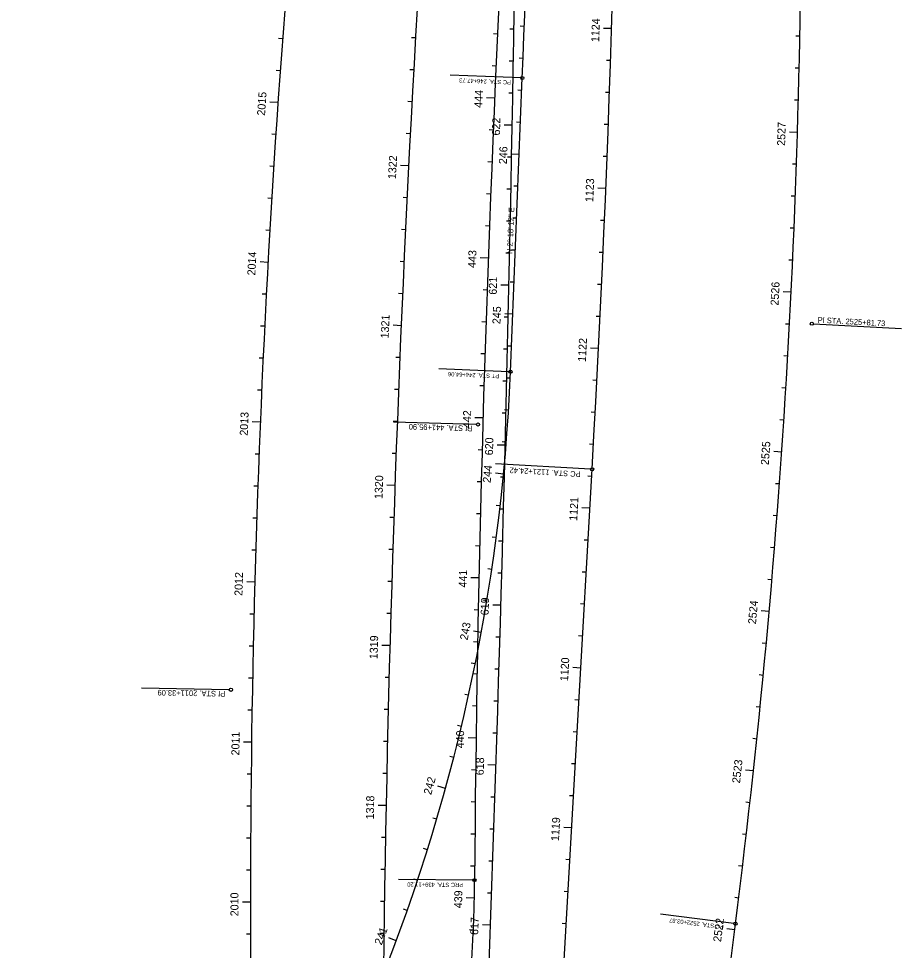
# Model space of a CAD drawing. Extents: x 919452 to 931278, y 583254 to 665650.
# Drawn here: x 928794 to 929346, y 637530 to 638112 of the extents above; entities that cross this region are included whole.
import ezdxf

# ---------------------------------------------------------------- set-up
doc = ezdxf.new("R2010")
doc.units = 0
for name, color, linetype in [('CLConst_dp', 7, 'Continuous'), ('CurveDataLabel_dp', 7, 'Continuous'), ('StationTicL_dp', 7, 'Continuous'), ('StationTicS_dp', 7, 'Continuous'), ('TextBLStation', 7, 'Continuous'), ('TextLabel', 7, 'Continuous')]:
    doc.layers.add(name, color=color, linetype=linetype)

msp = doc.modelspace()

# ---------------------------------------------------------------- linework, layer by layer
at = {"layer": 'CLConst_dp'}
for p, q in [((929101.42, 637891.3), (929108.8, 638074.83)), ((929063.91, 636273.75), (929152.38, 637830.35)), ((929141.47, 636757.31), (929241.91, 637546.46))]:
    msp.add_line(p, q, dxfattribs=at)
for centre, radius, start, end in [((918208.05, 638452.43), 10962, 356.746791, 3.806041), ((914272.82, 638671.54), 14847.97, 357.696753, 0.946314), ((900459.43, 638571.38), 28647.89, 355.955427, 0.622371), ((942221.08, 637355.55), 13200, 175.794488, 180.562502), ((924158.91, 638193.39), 5124, 352.74679, 1.18191), ((942581.4, 637470.03), 13502.86, 177.14455, 179.560307), ((936146.52, 637562.53), 7207.49, 175.47906, 182.456288), ((927949.43, 637937.64), 1152.92, 317.11857, 357.69675), ((928044.2, 637581.6), 1034.77, 344.85215, 359.56031)]:
    msp.add_arc(centre, radius, start, end, dxfattribs=at)
at = {"layer": 'CurveDataLabel_dp'}
for p, q in [((929107.8, 638074.87), (929063.82, 638076.64)), ((929290.62, 637921.24), (929345.52, 637918.33)), ((929100.42, 637891.34), (929056.57, 637893.11)), ((929080.12, 637858.38), (929028.39, 637859.87)), ((929151.39, 637830.41), (929091.99, 637833.78)), ((928925.82, 637692.64), (928870.93, 637693.63)), ((929077.93, 637573.66), (929031.41, 637574.02)), ((929240.92, 637546.59), (929195.04, 637552.42))]:
    msp.add_line(p, q, dxfattribs=at)
for centre in [(929108.8, 638074.83), (929289.62, 637921.3), (929101.42, 637891.3), (929081.12, 637858.35), (929152.38, 637830.35), (928926.82, 637692.63), (929078.93, 637573.66), (929241.91, 637546.46)]:
    msp.add_circle(centre, 1, dxfattribs=at)
at = {"layer": 'StationTicL_dp'}
for p, q in [((929164.56, 638105.66), (929159.57, 638105.81)), ((928956.18, 638059.45), (928951.19, 638059.79)), ((929091.53, 638062.27), (929086.53, 638062.49)), ((929102.49, 638045.33), (929097.49, 638045.42)), ((929280.64, 638040.88), (929275.65, 638041.03)), ((929106.88, 638027.13), (929101.88, 638027.33)), ((929037.81, 638019.97), (929032.82, 638020.23)), ((929160.94, 638005.72), (929155.95, 638005.92)), ((928949.97, 637959.64), (928944.98, 637959.92)), ((929087.51, 637962.35), (929082.52, 637962.53)), ((929100.47, 637945.35), (929095.48, 637945.46)), ((929276.69, 637940.96), (929271.7, 637941.21)), ((929102.86, 637927.21), (929097.87, 637927.41)), ((929033.15, 637920.08), (929028.16, 637920.3)), ((929156.41, 637905.82), (929151.42, 637906.07)), ((929084.24, 637862.41), (929079.24, 637862.55)), ((928945.16, 637859.76), (928940.16, 637859.96)), ((929098.12, 637845.37), (929093.12, 637845.5)), ((929270.79, 637841.14), (929265.8, 637841.48)), ((929097.07, 637827.4), (929092.09, 637827.87)), ((929029.26, 637820.16), (929024.26, 637820.34)), ((929151, 637805.97), (929146.01, 637806.25)), ((929081.7, 637762.44), (929076.7, 637762.55)), ((928941.73, 637759.82), (928936.73, 637759.96)), ((929095.41, 637745.41), (929090.41, 637745.55)), ((929262.94, 637741.45), (929257.96, 637741.89)), ((929083.2, 637728.39), (929078.29, 637729.3)), ((929026.11, 637720.21), (929021.12, 637720.35)), ((929145.32, 637706.13), (929140.33, 637706.42)), ((928939.68, 637659.84), (928934.68, 637659.91)), ((929079.91, 637662.45), (929074.91, 637662.53)), ((929092.35, 637645.46), (929087.35, 637645.62)), ((929253.15, 637641.93), (929248.18, 637642.47)), ((929060.81, 637630.96), (929055.99, 637632.29)), ((929023.73, 637620.24), (929018.73, 637620.34)), ((929139.65, 637606.29), (929134.66, 637606.58)), ((928939.03, 637559.84), (928934.03, 637559.84)), ((929078.79, 637562.46), (929073.79, 637562.55)), ((929088.94, 637545.52), (929083.95, 637545.69)), ((929241.42, 637542.62), (929236.46, 637543.25)), ((929030.07, 637535.84), (929025.38, 637537.58))]:
    msp.add_line(p, q, dxfattribs=at)
at = {"layer": 'StationTicS_dp'}
for p, q in [((929103.52, 638105.32), (929101.02, 638105.36)), ((929110.06, 638107.07), (929107.56, 638107.16)), ((928959.04, 638099.35), (928956.55, 638099.53)), ((929042.08, 638099.86), (929039.58, 638100)), ((929093.34, 638102.23), (929090.84, 638102.35)), ((929282.08, 638100.87), (929279.58, 638100.91)), ((929092.42, 638082.25), (929089.92, 638082.36)), ((929103.19, 638085.32), (929100.69, 638085.36)), ((929109.29, 638087.08), (929106.79, 638087.18)), ((929163.91, 638085.67), (929161.41, 638085.75)), ((928957.58, 638079.4), (928955.09, 638079.58)), ((929040.97, 638079.89), (929038.47, 638080.03)), ((929281.68, 638080.87), (929279.18, 638080.92)), ((929102.85, 638065.32), (929100.35, 638065.37)), ((929108.49, 638067.1), (929105.99, 638067.2)), ((929163.22, 638065.68), (929160.73, 638065.77)), ((929039.88, 638059.92), (929037.39, 638060.05)), ((929281.2, 638060.88), (929278.7, 638060.94)), ((929107.68, 638047.11), (929105.19, 638047.22)), ((929090.67, 638042.29), (929088.17, 638042.4)), ((929162.5, 638045.69), (929160, 638045.78)), ((928954.82, 638039.49), (928952.33, 638039.66)), ((929038.83, 638039.95), (929036.33, 638040.08)), ((929102.11, 638025.33), (929099.61, 638025.38)), ((929161.74, 638025.71), (929159.24, 638025.8)), ((928953.53, 638019.54), (928951.03, 638019.69)), ((929089.83, 638022.31), (929087.33, 638022.41)), ((929280.01, 638020.89), (929277.51, 638020.98)), ((929106.08, 638007.15), (929103.58, 638007.25)), ((929089.03, 638002.32), (929086.53, 638002.42)), ((929101.72, 638005.33), (929099.22, 638005.38)), ((929279.3, 638000.91), (929276.8, 638001)), ((928952.29, 637999.57), (928949.79, 637999.73)), ((929036.82, 638000), (929034.32, 638000.12)), ((929101.32, 637985.34), (929098.82, 637985.39)), ((929105.27, 637987.16), (929102.78, 637987.26)), ((929160.11, 637985.74), (929157.61, 637985.85)), ((928951.1, 637979.61), (928948.61, 637979.75)), ((929035.86, 637980.02), (929033.36, 637980.14)), ((929088.26, 637982.34), (929085.76, 637982.43)), ((929278.51, 637980.92), (929276.01, 637981.03)), ((929100.9, 637965.34), (929098.41, 637965.39)), ((929104.47, 637967.18), (929101.97, 637967.28)), ((929159.24, 637965.76), (929156.74, 637965.87)), ((929034.93, 637960.04), (929032.43, 637960.16)), ((929277.64, 637960.94), (929275.14, 637961.05)), ((929086.8, 637942.36), (929084.3, 637942.45)), ((929103.67, 637947.2), (929101.17, 637947.3)), ((929158.33, 637945.78), (929155.84, 637945.89)), ((928948.9, 637939.67), (928946.4, 637939.8)), ((929034.02, 637940.06), (929031.53, 637940.18)), ((929100.03, 637925.35), (929097.53, 637925.41)), ((929157.39, 637925.8), (929154.89, 637925.92)), ((928947.88, 637919.7), (928945.38, 637919.82)), ((929086.11, 637922.38), (929083.61, 637922.46)), ((929275.67, 637920.99), (929273.17, 637921.12)), ((929102.06, 637907.23), (929099.56, 637907.33)), ((929085.46, 637902.39), (929082.96, 637902.47)), ((929099.57, 637905.36), (929097.07, 637905.41)), ((928946.92, 637899.72), (928944.42, 637899.84)), ((929032.31, 637900.1), (929029.82, 637900.2)), ((929274.57, 637901.02), (929272.07, 637901.16)), ((929099.1, 637885.36), (929096.6, 637885.42)), ((929101.25, 637887.24), (929098.75, 637887.35)), ((929155.4, 637885.85), (929152.9, 637885.98)), ((928946.01, 637879.74), (928943.51, 637879.85)), ((929031.5, 637880.12), (929029.01, 637880.22)), ((929084.83, 637882.4), (929082.33, 637882.47)), ((929273.39, 637881.05), (929270.89, 637881.21)), ((929100.2, 637867.27), (929097.7, 637867.42)), ((929098.62, 637865.37), (929096.12, 637865.43)), ((929154.35, 637865.88), (929151.85, 637866.01)), ((929272.13, 637861.09), (929269.63, 637861.26)), ((929030.72, 637860.13), (929028.23, 637860.23)), ((929098.81, 637847.32), (929096.31, 637847.52)), ((929153.26, 637845.91), (929150.76, 637846.05)), ((928944.36, 637839.77), (928941.86, 637839.87)), ((929029.98, 637840.15), (929027.48, 637840.24)), ((929083.67, 637842.41), (929081.17, 637842.48)), ((929152.13, 637825.94), (929149.64, 637826.08)), ((928943.62, 637819.79), (928941.12, 637819.88)), ((929083.13, 637822.42), (929080.63, 637822.49)), ((929097.6, 637825.38), (929095.1, 637825.45)), ((929269.38, 637821.19), (929266.88, 637821.37)), ((929082.63, 637802.43), (929080.13, 637802.49)), ((929094.98, 637807.51), (929092.5, 637807.79)), ((929097.07, 637805.39), (929094.57, 637805.45)), ((928942.93, 637799.8), (928940.43, 637799.88)), ((929028.57, 637800.17), (929026.07, 637800.26)), ((929267.89, 637801.24), (929265.39, 637801.44)), ((929092.55, 637787.65), (929090.07, 637787.98)), ((929096.53, 637785.39), (929094.03, 637785.46)), ((929149.86, 637786), (929147.37, 637786.15)), ((928942.3, 637779.81), (928939.8, 637779.89)), ((929027.91, 637780.18), (929025.41, 637780.26)), ((929082.15, 637782.43), (929079.65, 637782.49)), ((929266.32, 637781.31), (929263.82, 637781.51)), ((929089.78, 637767.85), (929087.31, 637768.22)), ((929095.98, 637765.4), (929093.48, 637765.47)), ((929148.73, 637766.04), (929146.23, 637766.18)), ((929027.28, 637760.19), (929024.78, 637760.27)), ((929264.67, 637761.37), (929262.18, 637761.58)), ((929086.66, 637748.09), (929084.2, 637748.5)), ((929147.59, 637746.07), (929145.1, 637746.21)), ((928941.21, 637739.83), (928938.71, 637739.89)), ((929026.68, 637740.2), (929024.18, 637740.27)), ((929081.28, 637742.44), (929078.78, 637742.49)), ((929080.89, 637722.45), (929078.39, 637722.49)), ((929094.82, 637725.42), (929092.32, 637725.49)), ((929146.46, 637726.1), (929143.96, 637726.24)), ((929261.14, 637721.53), (929258.65, 637721.76)), ((928940.74, 637719.83), (928938.24, 637719.88)), ((929079.4, 637708.76), (929076.95, 637709.26)), ((929094.23, 637705.43), (929091.73, 637705.5)), ((928940.33, 637699.83), (928937.83, 637699.88)), ((929025.58, 637700.22), (929023.08, 637700.28)), ((929080.53, 637702.45), (929078.03, 637702.49)), ((929259.26, 637701.62), (929256.77, 637701.86)), ((929075.26, 637689.19), (929072.82, 637689.73)), ((929144.19, 637686.16), (929141.69, 637686.31)), ((929025.07, 637680.22), (929022.57, 637680.28)), ((929080.2, 637682.45), (929077.71, 637682.49)), ((929093.61, 637685.44), (929091.11, 637685.51)), ((929257.3, 637681.71), (929254.81, 637681.96)), ((928939.98, 637679.84), (928937.48, 637679.88)), ((929070.78, 637669.7), (929068.35, 637670.28)), ((929092.99, 637665.45), (929090.49, 637665.53)), ((929143.05, 637666.2), (929140.56, 637666.34)), ((929024.59, 637660.23), (929022.09, 637660.29)), ((929255.27, 637661.82), (929252.78, 637662.08)), ((929065.97, 637650.29), (929063.54, 637650.91)), ((929141.92, 637646.23), (929139.42, 637646.37)), ((928939.44, 637639.84), (928936.94, 637639.87)), ((929024.15, 637640.23), (929021.65, 637640.29)), ((929079.63, 637642.46), (929077.14, 637642.49)), ((929079.39, 637622.46), (929076.89, 637622.49)), ((929091.7, 637625.47), (929089.2, 637625.55)), ((929140.78, 637626.26), (929138.29, 637626.4)), ((929250.96, 637622.05), (929248.48, 637622.33)), ((928939.25, 637619.84), (928936.75, 637619.86)), ((929055.33, 637611.73), (929052.93, 637612.44)), ((929091.03, 637605.48), (929088.53, 637605.56)), ((928939.12, 637599.84), (928936.62, 637599.86)), ((929023.35, 637600.24), (929020.85, 637600.29)), ((929079.18, 637602.46), (929076.68, 637602.48)), ((929248.69, 637602.18), (929246.21, 637602.47)), ((929049.51, 637592.6), (929047.12, 637593.35)), ((929079, 637582.46), (929076.5, 637582.48)), ((929090.35, 637585.49), (929087.85, 637585.58)), ((929138.51, 637586.33), (929136.02, 637586.47)), ((929246.35, 637582.32), (929243.86, 637582.62)), ((928939.05, 637579.84), (928936.55, 637579.85)), ((929022.99, 637580.25), (929020.49, 637580.29)), ((929043.36, 637573.57), (929040.98, 637574.36)), ((929089.65, 637565.5), (929087.15, 637565.59)), ((929137.38, 637566.36), (929134.88, 637566.5)), ((929022.66, 637560.25), (929020.16, 637560.29)), ((929243.92, 637562.47), (929241.44, 637562.77)), ((929036.88, 637554.65), (929034.52, 637555.48)), ((929136.24, 637546.39), (929133.75, 637546.53)), ((929078.22, 637542.47), (929075.72, 637542.56)), ((928939.06, 637539.84), (928936.56, 637539.84)), ((929022.37, 637540.25), (929019.87, 637540.28))]:
    msp.add_line(p, q, dxfattribs=at)

# ---------------------------------------------------------------- texts
at = {"layer": 'CurveDataLabel_dp'}
for s, height, rotation, p in [('PC STA. 246+47.73', 2.625, 177.69675, (929101.73, 638073.36)), ('PI STA. 2525+81.73', 3.5, 356.96435, (929293.16, 637921.99)), ('PT STA. 244+64.06', 2.625, 177.69675, (929094.35, 637889.84)), ('PI STA. 441+95.90', 3.5, 178.35243, (929077.59, 637857.58)), ('PC STA. 1121+24.42', 3.5, 176.74679, (929145.3, 637829)), ('PI STA. 2011+33.09', 3.5, 178.96767, (928923.3, 637691.81)), ('PRC STA. 439+11.20', 2.625, 179.56031, (929071.92, 637571.96)), ('PC STA. 2522+03.87', 2.625, 172.74679, (929234.75, 637545.61))]:
    msp.add_text(s, height=height, rotation=rotation, dxfattribs=at).set_placement(p)
at = {"layer": 'TextBLStation'}
for s, rotation, p in [('1124', 88.1872, (929156.79, 638097.17)), ('2015', 86.04664, (928948.09, 638051.18)), ('444', 87.4862, (929083.75, 638056.12)), ('622', 88.94782, (929094.87, 638038.88)), ('2527', 88.29446, (929272.89, 638032.39)), ('246', 87.69675, (929099.12, 638020.9)), ('1322', 87.11477, (929029.87, 638011.53)), ('1123', 87.66452, (929153.09, 637997.2)), ('2014', 86.84158, (928942, 637951.34)), ('443', 87.91052, (929079.78, 637956.04)), ('621', 88.74782, (929092.84, 637939.38)), ('2526', 87.17628, (929268.77, 637932.56)), ('245', 87.69675, (929095.1, 637920.95)), ('1321', 87.54883, (929025.3, 637912.03)), ('1122', 87.14184, (929148.48, 637897.38)), ('442', 88.33484, (929076.55, 637856.04)), ('2013', 87.63653, (928937.3, 637851.24)), ('620', 88.54782, (929090.45, 637839.04)), ('2525', 86.0581, (929262.7, 637832.86)), ('244', 84.51303, (929088.98, 637821.66)), ('1320', 87.98289, (929021.45, 637811.66)), ('1121', 86.74679, (929143.03, 637798.03)), ('2012', 88.43148, (928933.99, 637751.2)), ('441', 88.75917, (929074.07, 637756.47)), ('619', 88.34782, (929087.72, 637739.1)), ('2524', 84.93991, (929254.7, 637733.41)), ('243', 79.54338, (929074.63, 637723.28)), ('1319', 88.41695, (929018.38, 637711.64)), ('1120', 86.74679, (929137.34, 637697.8)), ('2011', 89.22643, (928932.07, 637651.56)), ('440', 89.18349, (929072.31, 637656.04)), ('618', 88.14782, (929084.64, 637639.13)), ('2523', 83.82173, (929244.74, 637633.95)), ('242', 74.57374, (929051.83, 637626.61)), ('1318', 88.85101, (929016.06, 637611.57)), ('1119', 86.74679, (929131.66, 637597.96)), ('2010', 90.02137, (928931.53, 637551.07)), ('439', 88.94038, (929071.17, 637556.07)), ('617', 87.94782, (929081.22, 637539.32)), ('2522', 82.74679, (929232.87, 637534.81)), ('241', 69.6041, (929020.9, 637532.7))]:
    msp.add_text(s, height=5, rotation=rotation, dxfattribs=at).set_placement(p)
at = {"layer": 'TextLabel'}
msp.add_text('N 2%%d 18\' 12" E', height=3.5, rotation=87.69675, dxfattribs=at).set_placement((929102.62, 637964.83))

doc.saveas('drawing.dxf')
